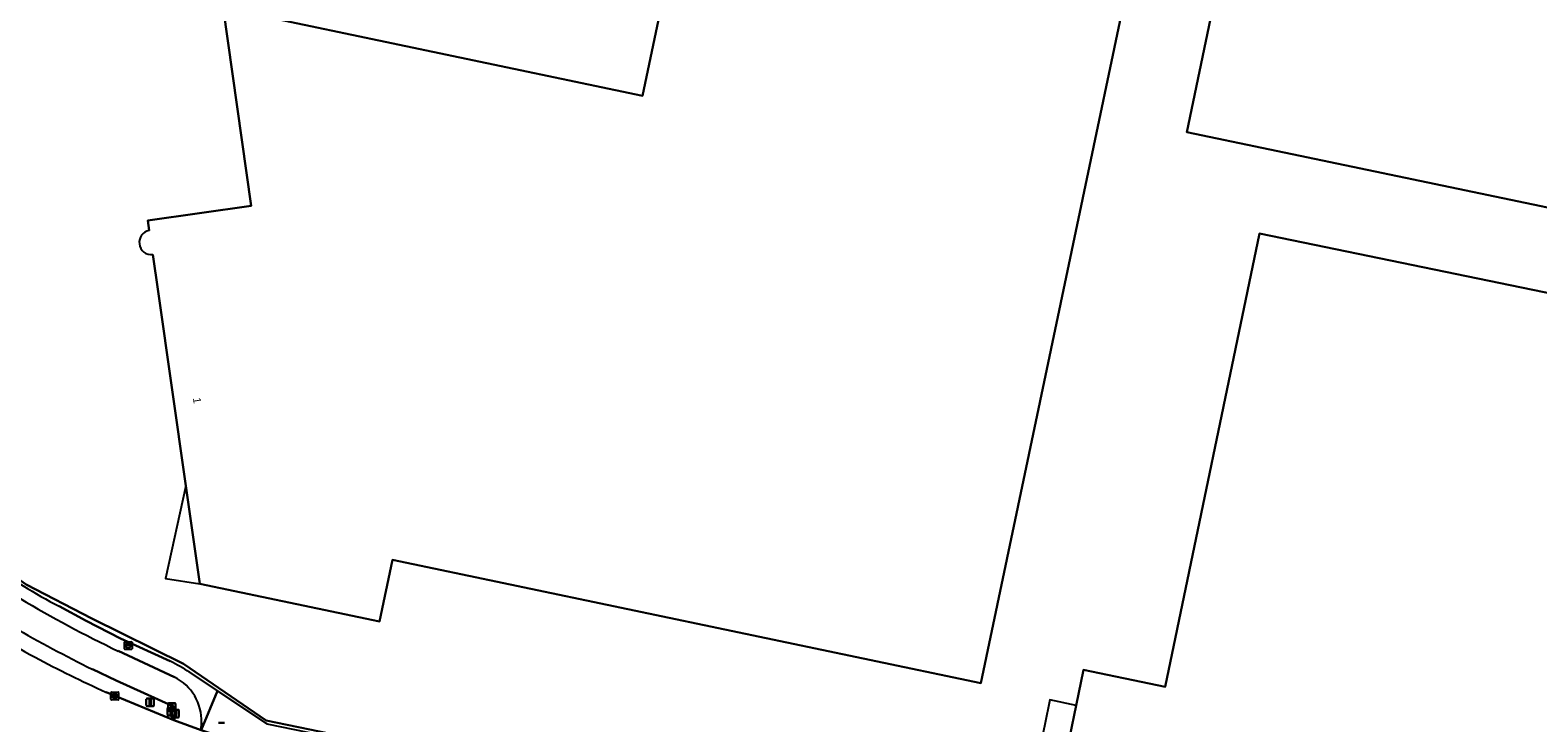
# Model space of a CAD drawing. Extents: x 157692 to 159674, y 381452 to 383291.
# Drawn here: x 157908.9 to 158104.5, y 382250.2 to 382340.2 of the extents above; entities that cross this region are included whole.
import ezdxf

# ---------------------------------------------------------------- set-up
doc = ezdxf.new("R2010")
doc.units = 0
for name, color, linetype in [('IMGEO_Berm_groen', 7, 'Continuous'), ('IMGEO_Brandkraan', 7, 'Continuous'), ('IMGEO_Drukknoppaal', 7, 'Continuous'), ('IMGEO_Erf', 7, 'Continuous'), ('IMGEO_Fietspad_open', 7, 'Continuous'), ('IMGEO_Grasland_overig', 7, 'Continuous'), ('IMGEO_Hek', 7, 'Continuous'), ('IMGEO_Kolk', 7, 'Continuous'), ('IMGEO_Pand', 7, 'Continuous'), ('IMGEO_Pand_nummerreeks', 7, 'Continuous'), ('IMGEO_Pand_overbouw', 7, 'Continuous'), ('IMGEO_Portaal', 7, 'Continuous'), ('IMGEO_Rijbaan_regionaal_gesloten', 7, 'Continuous'), ('IMGEO_Verkeersbordpaal', 7, 'Continuous'), ('IMGEO_Verkeersregelinstallatiepaal', 7, 'Continuous'), ('IMGEO_Voetpad_open', 7, 'Continuous')]:
    doc.layers.add(name, color=color, linetype=linetype)

msp = doc.modelspace()

# ---------------------------------------------------------------- linework, layer by layer
at = {"layer": 'IMGEO_Berm_groen'}
for points in [[(157927.29, 382252.42), (157920.03, 382255.69), (157916.93, 382257.17)], [(157918.7, 382254.18), (157927.48, 382250.55), (157927.8, 382251.21)]]:
    msp.add_lwpolyline(points, dxfattribs=at)
for centre, radius, start, end in [((157984.01, 382396.64), 156.76, 237.1249, 241.6163), ((157996.5, 382418.22), 179.64, 240.0076, 243.7049), ((157981.64, 382393.24), 152.64, 241.7926, 245.6464), ((157926.87, 382251.54), 0.985, 340.5895, 64.3888)]:
    msp.add_arc(centre, radius, start, end, dxfattribs=at)
at = {"layer": 'IMGEO_Brandkraan'}
for p, q in [((157921.08, 382259.82), (157921.08, 382260.67)), ((157921.15, 382260.74), (157922, 382260.74)), ((157921.33, 382260.24), (157921.33, 382260.25)), ((157921.38, 382260.29), (157921.77, 382260.29)), ((157921.56, 382260.52), (157921.59, 382260.52)), ((157921.82, 382260.25), (157921.82, 382260.24)), ((157922.08, 382260.67), (157922.08, 382259.82)), ((157922, 382259.74), (157921.15, 382259.74)), ((157921.77, 382260.2), (157921.37, 382260.2)), ((157921.59, 382259.96), (157921.56, 382259.96))]:
    msp.add_line(p, q, dxfattribs=at)
for points in [[(157921.08, 382259.82), (157921.08, 382260.67)], [(157921.15, 382260.74), (157922, 382260.74)], [(157922.08, 382260.67), (157922.08, 382259.82)], [(157922, 382259.74), (157921.15, 382259.74)]]:
    msp.add_lwpolyline(points, dxfattribs=at)
for centre, radius, start, end in [((157921.15, 382260.67), 0.0765, 91.552, 178.448), ((157921.15, 382260.67), 0.0765, 91.552, 178.448), ((157921.37, 382260.25), 0.0403, 85.8775, 175.7526), ((157921.37, 382260.24), 0.0366, 178.938, 274.7102), ((157921.78, 382260.25), 0.0386, 1.7309, 96.639), ((157921.78, 382260.24), 0.043, 264.8664, 352.4533), ((157922, 382260.67), 0.0765, 1.552, 88.448), ((157922, 382260.67), 0.0765, 1.552, 88.448), ((157921.15, 382259.82), 0.0765, 181.552, 268.448), ((157921.15, 382259.82), 0.0765, 181.552, 268.448), ((157922, 382259.82), 0.0765, 271.552, 358.448), ((157922, 382259.82), 0.0765, 271.552, 358.448)]:
    msp.add_arc(centre, radius, start, end, dxfattribs=at)
for centre, major_axis, ratio, start_param, end_param in [((157921.56, 382260.24), (-0.387, 0.002), 0.722429, 4.712389, 7.853982), ((157921.59, 382260.24), (-0.39, 0.002), 0.717154, 1.570796, 4.712389)]:
    msp.add_ellipse(centre, major_axis=major_axis, ratio=ratio, start_param=start_param, end_param=end_param, dxfattribs=at)
at = {"layer": 'IMGEO_Drukknoppaal'}
for p, q in [((157926.75, 382251.86), (157926.75, 382252.65)), ((157926.75, 382252.65), (157926.75, 382251.86)), ((157926.85, 382252.75), (157927.63, 382252.75)), ((157927.63, 382252.75), (157926.85, 382252.75)), ((157927.73, 382252.65), (157927.73, 382251.86)), ((157927.73, 382251.86), (157927.73, 382252.65)), ((157927.63, 382251.76), (157926.85, 382251.76)), ((157926.85, 382251.76), (157927.63, 382251.76))]:
    msp.add_line(p, q, dxfattribs=at)
msp.add_lwpolyline([(157927.16, 382252.63), (157927.32, 382252.63), (157927.32, 382251.88), (157927.16, 382251.88), (157927.16, 382252.63)], dxfattribs=at)
for centre, start, end in [((157926.85, 382252.65), 90, 180), ((157926.85, 382252.65), 90, 180), ((157927.63, 382252.65), 0, 90), ((157927.63, 382252.65), 360, 90), ((157926.85, 382251.86), 180, 270), ((157926.85, 382251.86), 180, 270), ((157927.63, 382251.86), 270, 0), ((157927.63, 382251.86), 270, 0)]:
    msp.add_arc(centre, 0.1, start, end, dxfattribs=at)
at = {"layer": 'IMGEO_Erf'}
for points in [[(157924.3, 382314.16), (157924.12, 382315.46), (157937.55, 382317.33), (157933.9, 382343.05), (157988.31, 382331.62), (158006.84, 382419.65), (158064.19, 382407.61), (158032.2, 382255.36)], [(157882.04, 382363.73), (157890.31, 382303.27), (157892.25, 382289.09), (157893.24, 382282.29), (157893.69, 382278.44), (157908.35, 382268.17), (157916.85, 382263.75), (157928.76, 382257.88), (157939.46, 382250.49), (158076.24, 382222.29), (158077.52, 382222.1), (158103.67, 382210.06), (158178.42, 382194.72), (158193.12, 382191.69), (158194.23, 382193.79), (158194.66, 382195.85), (158197.12, 382207.67), (158199.84, 382221.5), (158201.26, 382228.47), (158202.31, 382233.55), (158203.97, 382241.69), (158205.66, 382250), (158208.13, 382262.14)], [(158032.2, 382255.36), (157955.86, 382271.39), (157954.19, 382263.38), (157930.89, 382268.26), (157929.06, 382280.97), (157925.47, 382306.23), (157924.77, 382311.01)]]:
    msp.add_lwpolyline(points, dxfattribs=at)
for points in [[(158072.5, 382391.84), (158082.45, 382389.68), (158094.2, 382387.27), (158096.6, 382398.7), (158095.42, 382398.96), (158097.72, 382410.07), (158147.64, 382399.66), (158145.32, 382388.54), (158144.12, 382388.78), (158141.76, 382377.34), (158153.45, 382374.85), (158152.43, 382369.95), (158143.09, 382324.94), (158142.37, 382321.46), (158136.53, 382322.68), (158134.13, 382311.19), (158058.96, 382326.9)], [(158191.55, 382288.32), (158183.63, 382250), (158178.3, 382224.18), (158109.97, 382238.3), (158105, 382239.32), (158103.5, 382231.98), (158081.67, 382236.49), (158081.85, 382237.37), (158078.93, 382237.98), (158078.68, 382236.85), (158053.51, 382242.03), (158053.56, 382242.29), (158042.93, 382244.5), (158044.57, 382252.45), (158045.53, 382257.07), (158056.12, 382254.86), (158068.35, 382313.75)]]:
    msp.add_lwpolyline(points, close=True, dxfattribs=at)
for centre, radius, start, end in [((157924.58, 382312.62), 1.56, 100.1947, 188.2803), ((157924.58, 382312.55), 1.55, 185.6182, 276.9008)]:
    msp.add_arc(centre, radius, start, end, dxfattribs=at)
at = {"layer": 'IMGEO_Fietspad_open'}
for points in [[(157927.59, 382256.11), (157920.28, 382259.53)], [(157916.93, 382257.17), (157920.03, 382255.69), (157927.29, 382252.42)], [(157927.8, 382251.21), (157927.48, 382250.55), (157931.06, 382249.26), (157931.08, 382250.23)]]:
    msp.add_lwpolyline(points, dxfattribs=at)
for centre, radius, start, end in [((157988.67, 382402.8), 158.76, 239.2679, 244.4835), ((157996.5, 382418.22), 179.64, 240.0076, 243.7049), ((157924.82, 382250.5), 6.26, 357.5933, 63.7566), ((157926.87, 382251.54), 0.985, 340.5895, 64.3888)]:
    msp.add_arc(centre, radius, start, end, dxfattribs=at)
at = {"layer": 'IMGEO_Grasland_overig'}
for points in [[(157939.46, 382250.49), (157928.76, 382257.88), (157916.85, 382263.75), (157908.35, 382268.17), (157893.69, 382278.44), (157893.74, 382277.94), (157895.14, 382276.8)], [(157912.6, 382265.34), (157916.12, 382263.43), (157920.56, 382261.17), (157927.03, 382258.19)], [(157929.54, 382256.76), (157933.18, 382254.34), (157939.57, 382250.09), (158076.98, 382221.9), (158102.01, 382210.4), (158103.67, 382210.06), (158077.52, 382222.1), (158076.24, 382222.29), (157939.46, 382250.49)]]:
    msp.add_lwpolyline(points, dxfattribs=at)
for centre, radius, start, end in [((157956.04, 382347.25), 92.72, 235.4592, 242.0631), ((157920.14, 382243.14), 16.55, 55.4114, 65.4236)]:
    msp.add_arc(centre, radius, start, end, dxfattribs=at)
at = {"layer": 'IMGEO_Hek'}
for points in [[(157916.85, 382263.75), (157908.35, 382268.17), (157893.81, 382278.35), (157893.24, 382282.29)], [(158076.24, 382222.29), (157939.46, 382250.49), (157928.76, 382257.88), (157916.85, 382263.75)]]:
    msp.add_lwpolyline(points, dxfattribs=at)
at = {"layer": 'IMGEO_Kolk'}
for p, q in [((157919.34, 382253.26), (157919.34, 382254.11)), ((157919.41, 382254.18), (157920.27, 382254.18)), ((157920.27, 382253.18), (157919.41, 382253.18)), ((157919.6, 382253.68), (157919.6, 382253.69)), ((157919.64, 382253.73), (157920.04, 382253.73)), ((157920.04, 382253.64), (157919.64, 382253.64)), ((157919.85, 382253.4), (157919.82, 382253.4)), ((157919.83, 382253.96), (157919.85, 382253.96)), ((157920.08, 382253.69), (157920.08, 382253.68)), ((157920.34, 382254.11), (157920.34, 382253.26))]:
    msp.add_line(p, q, dxfattribs=at)
for points in [[(157919.34, 382253.26), (157919.34, 382254.11)], [(157919.41, 382254.18), (157920.27, 382254.18)], [(157920.27, 382253.18), (157919.41, 382253.18)], [(157920.34, 382254.11), (157920.34, 382253.26)]]:
    msp.add_lwpolyline(points, dxfattribs=at)
for centre, radius, start, end in [((157919.42, 382254.11), 0.0765, 91.552, 178.448), ((157919.42, 382254.11), 0.0765, 91.552, 178.448), ((157919.42, 382253.26), 0.0765, 181.552, 268.448), ((157919.42, 382253.26), 0.0765, 181.552, 268.448), ((157919.64, 382253.69), 0.0403, 85.8775, 175.7526), ((157919.63, 382253.68), 0.0366, 178.938, 274.7102), ((157920.04, 382253.69), 0.0386, 1.7309, 96.639), ((157920.04, 382253.68), 0.043, 264.8664, 352.4533), ((157920.26, 382254.11), 0.0765, 1.552, 88.448), ((157920.26, 382254.11), 0.0765, 1.552, 88.448), ((157920.26, 382253.26), 0.0765, 271.552, 358.448), ((157920.26, 382253.26), 0.0765, 271.552, 358.448)]:
    msp.add_arc(centre, radius, start, end, dxfattribs=at)
for centre, major_axis, ratio, start_param, end_param in [((157919.83, 382253.68), (-0.387, 0.002), 0.722429, 4.712389, 7.853982), ((157919.85, 382253.68), (-0.39, 0.002), 0.717154, 1.570796, 4.712389)]:
    msp.add_ellipse(centre, major_axis=major_axis, ratio=ratio, start_param=start_param, end_param=end_param, dxfattribs=at)
at = {"layer": 'IMGEO_Pand'}
msp.add_lwpolyline([(157924.77, 382311.01), (157925.47, 382306.23), (157929.06, 382280.97), (157930.89, 382268.26), (157954.19, 382263.38), (157955.86, 382271.39), (158032.2, 382255.36), (158064.19, 382407.61), (158006.84, 382419.65), (157988.31, 382331.62), (157933.9, 382343.05), (157937.55, 382317.33), (157924.12, 382315.46), (157924.3, 382314.16)], dxfattribs=at)
for points in [[(158153.45, 382374.85), (158141.76, 382377.34), (158144.12, 382388.78), (158145.32, 382388.54), (158147.64, 382399.66), (158097.72, 382410.07), (158095.42, 382398.96), (158096.6, 382398.7), (158094.2, 382387.27), (158082.45, 382389.68), (158072.5, 382391.84), (158058.96, 382326.9), (158134.13, 382311.19), (158136.53, 382322.68), (158142.37, 382321.46), (158143.09, 382324.94), (158152.43, 382369.95)], [(158183.63, 382250), (158191.55, 382288.32), (158068.35, 382313.75), (158056.12, 382254.86), (158045.53, 382257.07), (158044.57, 382252.45), (158042.93, 382244.5), (158053.56, 382242.29), (158053.51, 382242.03), (158078.68, 382236.85), (158078.93, 382237.98), (158081.85, 382237.37), (158081.67, 382236.49), (158103.5, 382231.98), (158105, 382239.32), (158109.97, 382238.3), (158178.3, 382224.18)]]:
    msp.add_lwpolyline(points, close=True, dxfattribs=at)
for centre, radius, start, end in [((157924.58, 382312.62), 1.56, 100.1947, 188.2803), ((157924.58, 382312.55), 1.55, 185.6182, 276.9008)]:
    msp.add_arc(centre, radius, start, end, dxfattribs=at)
at = {"layer": 'IMGEO_Pand_overbouw'}
for points in [[(157929.06, 382280.97), (157926.4, 382268.95), (157930.89, 382268.26)], [(158081.67, 382236.49), (158081.85, 382237.37), (158078.93, 382237.98), (158078.68, 382236.85), (158053.51, 382242.03), (158053.56, 382242.29), (158042.93, 382244.5), (158044.57, 382252.45), (158041.15, 382253.18), (158040.5, 382250), (158039.18, 382243.66), (158047.48, 382241.92), (158055.81, 382240.33), (158064.17, 382238.88), (158078.45, 382236.78)]]:
    msp.add_lwpolyline(points, close=True, dxfattribs=at)
at = {"layer": 'IMGEO_Portaal'}
for p, q in [((157923.93, 382252.46), (157923.93, 382253.26)), ((157923.93, 382253.26), (157923.93, 382252.46)), ((157924.03, 382253.36), (157924.82, 382253.36)), ((157924.82, 382253.36), (157924.03, 382253.36)), ((157924.92, 382253.26), (157924.92, 382252.46)), ((157924.92, 382252.46), (157924.92, 382253.26)), ((157924.82, 382252.36), (157924.03, 382252.36)), ((157924.03, 382252.36), (157924.82, 382252.36))]:
    msp.add_line(p, q, dxfattribs=at)
msp.add_lwpolyline([(157924.35, 382253.24), (157924.5, 382253.24), (157924.5, 382252.49), (157924.35, 382252.49), (157924.35, 382253.24)], dxfattribs=at)
for centre, start, end in [((157924.03, 382253.26), 90, 180), ((157924.03, 382253.26), 90, 180), ((157924.03, 382252.46), 180, 270), ((157924.03, 382252.46), 180, 270), ((157924.82, 382253.26), 0, 90), ((157924.82, 382253.26), 360, 90), ((157924.82, 382252.46), 270, 0), ((157924.82, 382252.46), 270, 0)]:
    msp.add_arc(centre, 0.1, start, end, dxfattribs=at)
at = {"layer": 'IMGEO_Rijbaan_regionaal_gesloten'}
msp.add_lwpolyline([(157920.06, 382233.82), (157920.49, 382234.78), (157923.96, 382233.9), (157928.09, 382233.02), (157929.43, 382235.9), (157930.79, 382238.81), (157932.14, 382241.7), (157933.41, 382244.42), (157935.02, 382247.89), (157931.06, 382249.26), (157927.48, 382250.55), (157918.7, 382254.18)], dxfattribs=at)
for centre, radius, start, end in [((157984.01, 382396.64), 156.76, 237.1249, 241.6163), ((157981.64, 382393.24), 152.64, 241.7926, 245.6464)]:
    msp.add_arc(centre, radius, start, end, dxfattribs=at)
at = {"layer": 'IMGEO_Verkeersbordpaal'}
for p, q in [((157926.66, 382251.26), (157926.66, 382252.06)), ((157926.66, 382252.06), (157926.66, 382251.26)), ((157926.76, 382252.16), (157927.55, 382252.16)), ((157927.55, 382252.16), (157926.76, 382252.16)), ((157927.55, 382251.16), (157926.76, 382251.16)), ((157926.76, 382251.16), (157927.55, 382251.16)), ((157927.65, 382252.06), (157927.65, 382251.26)), ((157927.65, 382251.26), (157927.65, 382252.06))]:
    msp.add_line(p, q, dxfattribs=at)
msp.add_lwpolyline([(157927.08, 382252.03), (157927.23, 382252.03), (157927.23, 382251.28), (157927.08, 382251.28), (157927.08, 382252.03)], dxfattribs=at)
for centre, start, end in [((157926.76, 382252.06), 90, 180), ((157926.76, 382252.06), 90, 180), ((157926.76, 382251.26), 180, 270), ((157926.76, 382251.26), 180, 270), ((157927.55, 382252.06), 0, 90), ((157927.55, 382252.06), 360, 90), ((157927.55, 382251.26), 270, 0), ((157927.55, 382251.26), 270, 0)]:
    msp.add_arc(centre, 0.1, start, end, dxfattribs=at)
at = {"layer": 'IMGEO_Verkeersregelinstallatiepaal'}
for p, q in [((157927.17, 382251), (157927.17, 382251.8)), ((157927.17, 382251.8), (157927.17, 382251)), ((157927.27, 382251.9), (157928.06, 382251.9)), ((157928.06, 382251.9), (157927.27, 382251.9)), ((157928.06, 382250.9), (157927.27, 382250.9)), ((157927.27, 382250.9), (157928.06, 382250.9)), ((157928.16, 382251.8), (157928.16, 382251)), ((157928.16, 382251), (157928.16, 382251.8)), ((157933.28, 382250.19), (157934.07, 382250.19)), ((157934.07, 382250.19), (157933.28, 382250.19))]:
    msp.add_line(p, q, dxfattribs=at)
msp.add_lwpolyline([(157927.59, 382251.78), (157927.74, 382251.78), (157927.74, 382251.03), (157927.59, 382251.03), (157927.59, 382251.78)], dxfattribs=at)
for centre, start, end in [((157927.27, 382251.8), 90, 180), ((157927.27, 382251.8), 90, 180), ((157927.27, 382251), 180, 270), ((157927.27, 382251), 180, 270), ((157928.06, 382251.8), 0, 90), ((157928.06, 382251.8), 360, 90), ((157928.06, 382251), 270, 0), ((157928.06, 382251), 270, 0)]:
    msp.add_arc(centre, 0.1, start, end, dxfattribs=at)
at = {"layer": 'IMGEO_Voetpad_open'}
for points in [[(157927.03, 382258.19), (157920.56, 382261.17), (157916.12, 382263.43), (157912.6, 382265.34)], [(157920.28, 382259.53), (157927.59, 382256.11)], [(157931.08, 382250.23), (157931.06, 382249.26), (157933.18, 382254.34), (157929.54, 382256.76)], [(157939.57, 382250.09), (157933.18, 382254.34), (157931.06, 382249.26), (157935.02, 382247.89)]]:
    msp.add_lwpolyline(points, dxfattribs=at)
for centre, radius, start, end in [((157956.04, 382347.25), 92.72, 235.4592, 242.0631), ((157988.67, 382402.8), 158.76, 239.2679, 244.4835), ((157920.14, 382243.14), 16.55, 55.4114, 65.4236), ((157924.82, 382250.5), 6.26, 357.5933, 63.7566)]:
    msp.add_arc(centre, radius, start, end, dxfattribs=at)

# ---------------------------------------------------------------- texts
at = {"layer": 'IMGEO_Pand_nummerreeks'}
msp.add_text('1', height=1, rotation=278.1667, dxfattribs=at).set_placement((157929.98, 382292.37))

doc.saveas('drawing.dxf')
